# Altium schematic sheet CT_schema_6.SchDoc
size 478 x 453 mm
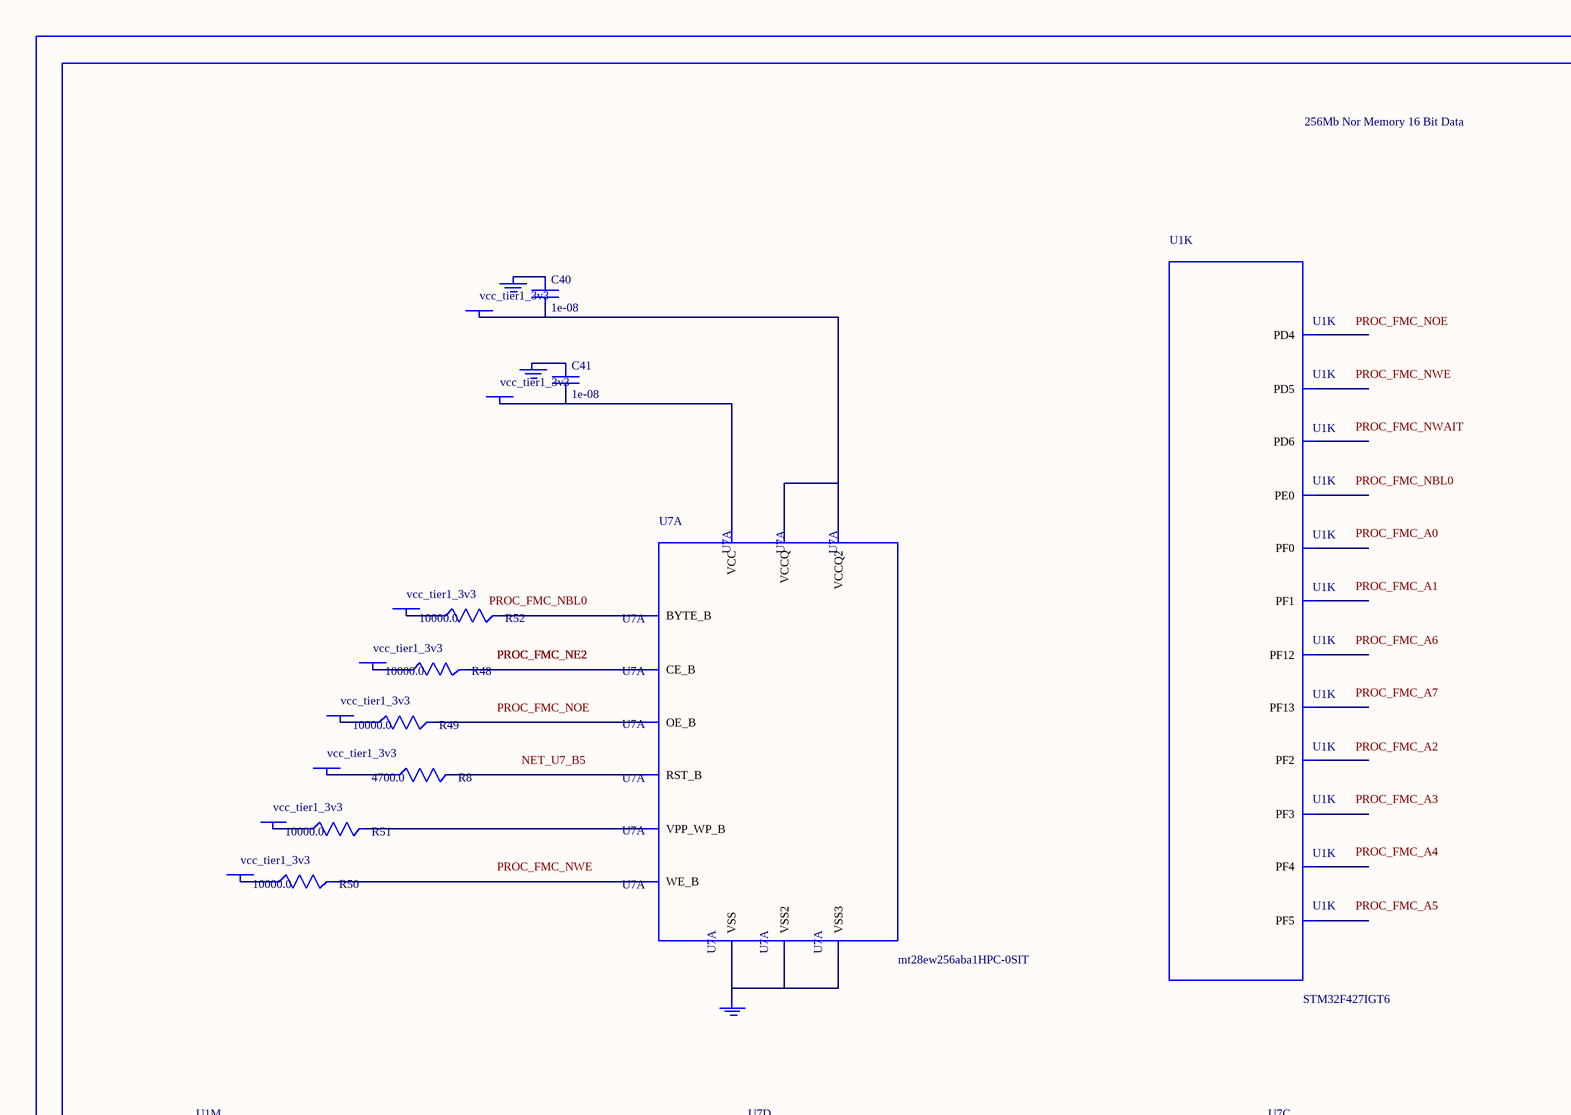
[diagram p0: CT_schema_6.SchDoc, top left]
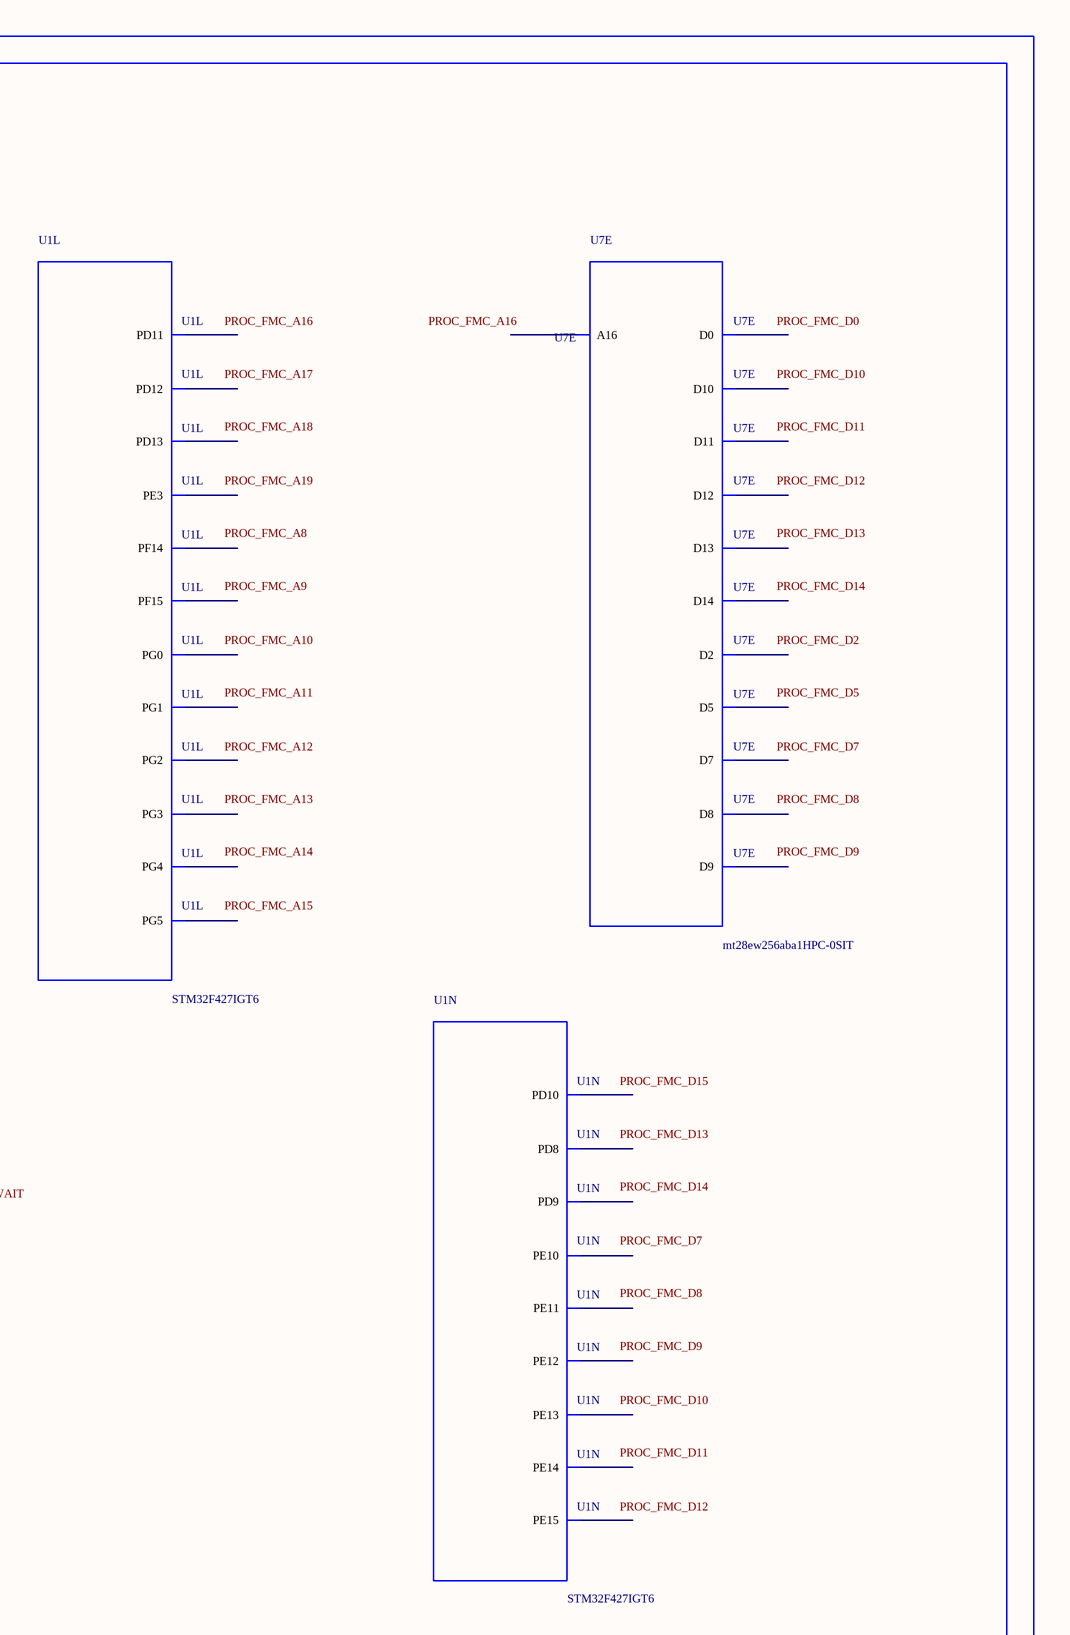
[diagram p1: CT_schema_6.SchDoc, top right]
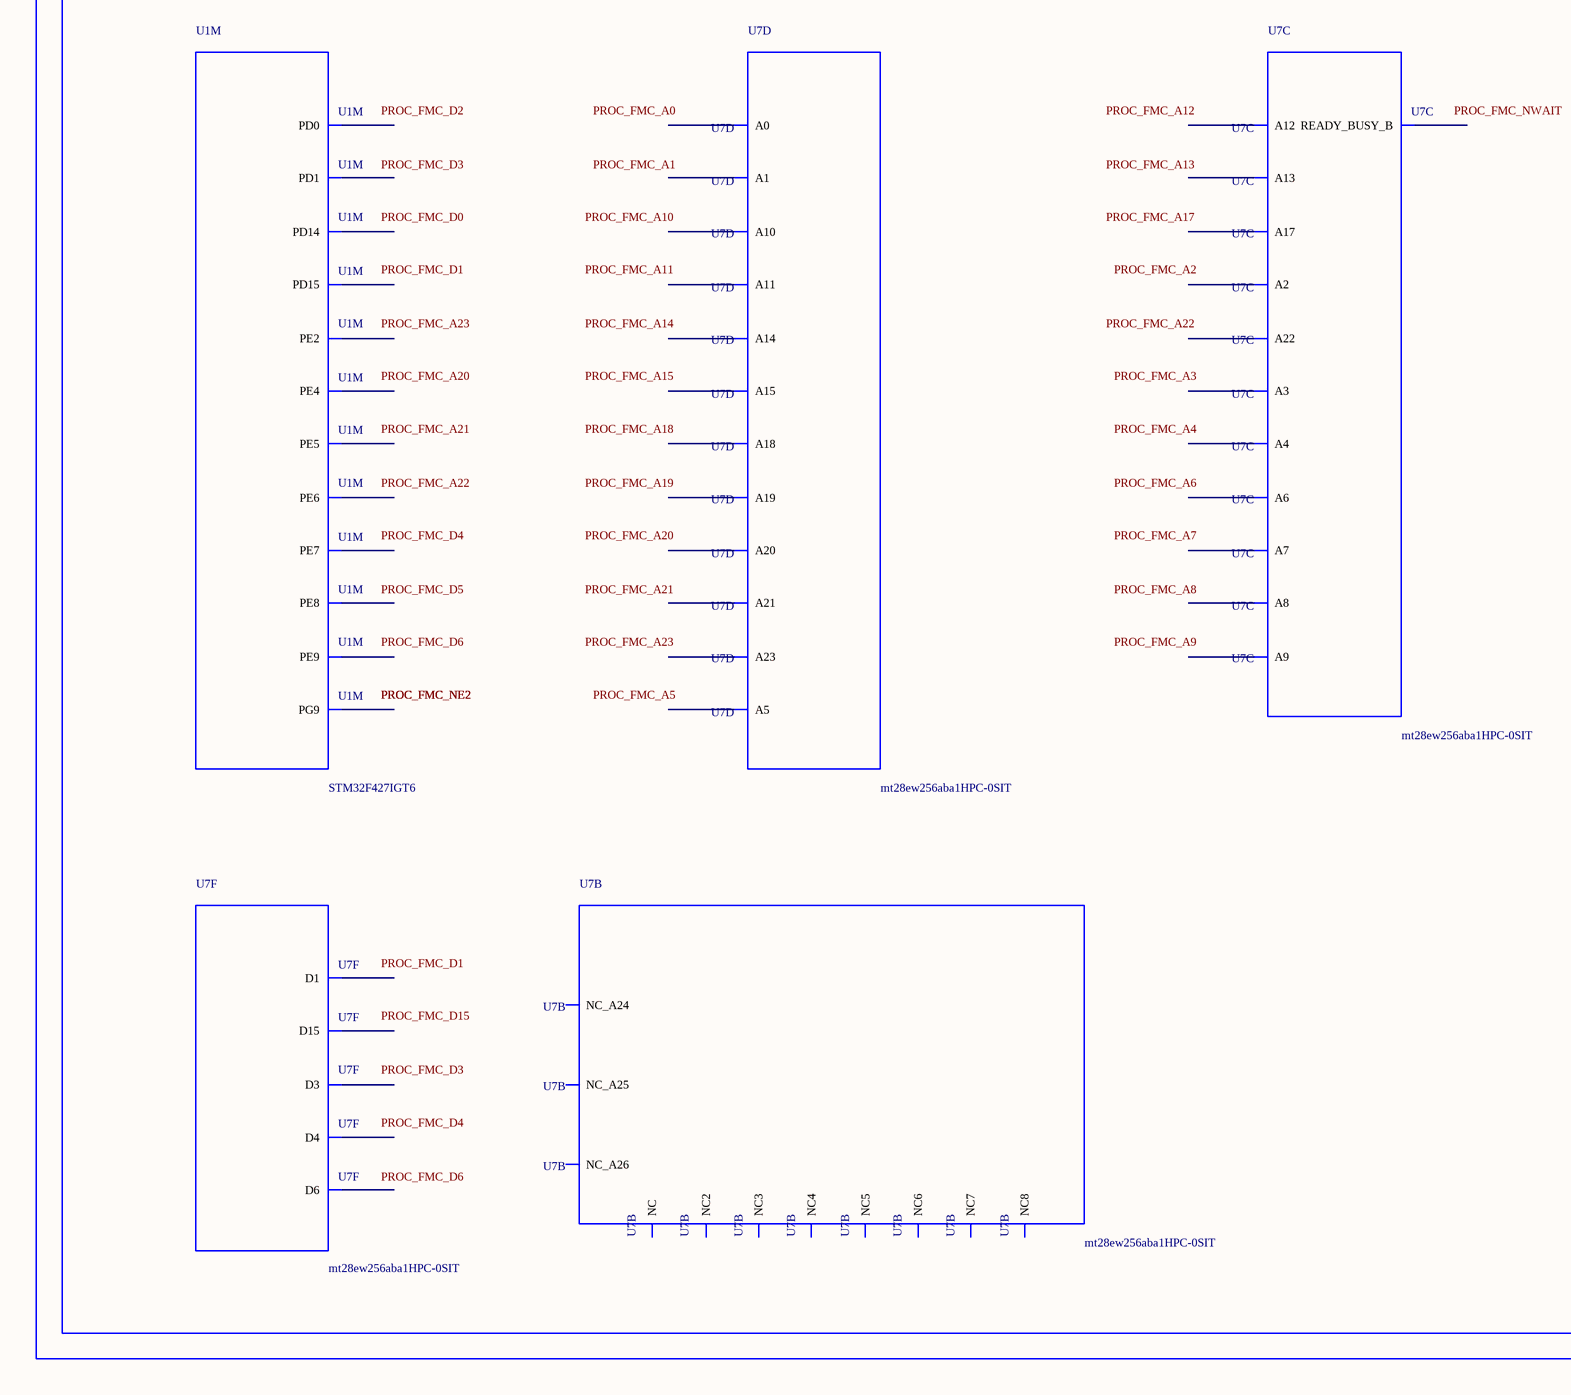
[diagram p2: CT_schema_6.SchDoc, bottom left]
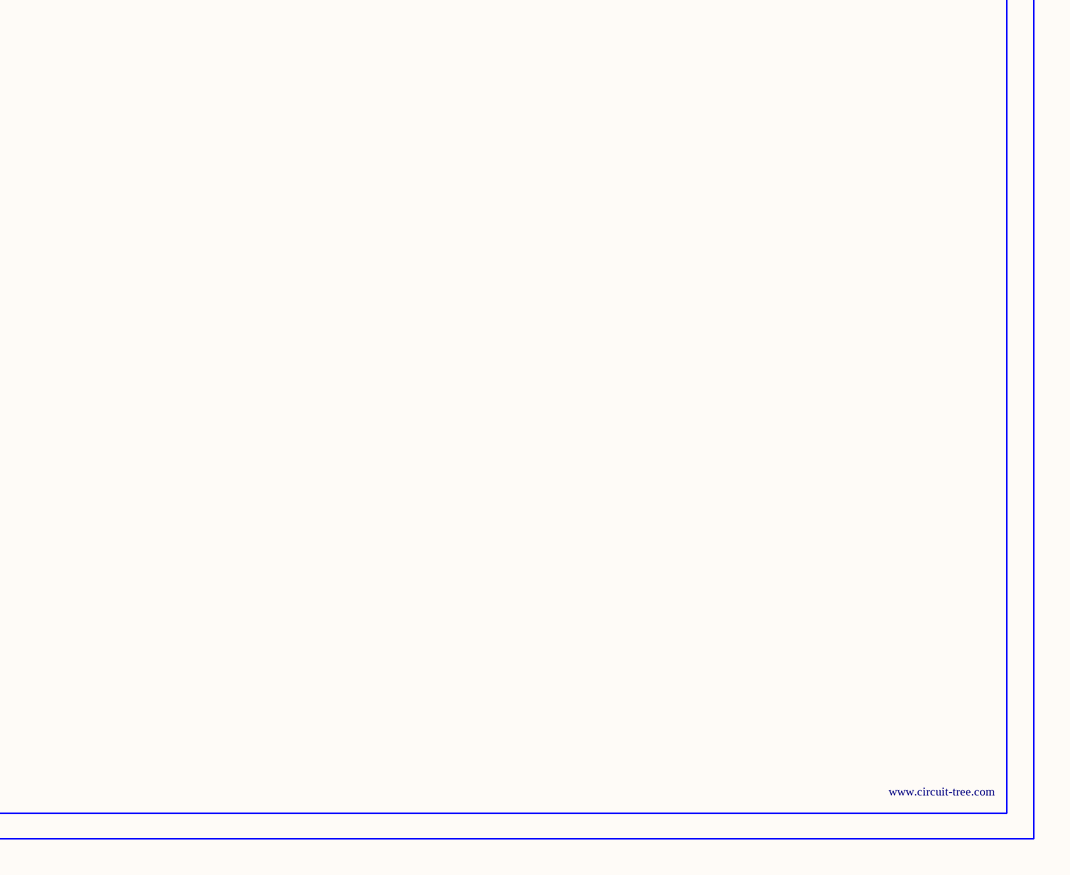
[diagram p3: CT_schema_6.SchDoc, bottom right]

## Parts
BORDER5  (no value)
C40  1e-08  [C0402]
C41  1e-08  [C0402]
GND_INSTANCE_5_0  (no value)
GND_INSTANCE_5_1  (no value)
GND_INSTANCE_5_2  (no value)
POWER_INSTANCE_5_0  vcc_tier1_3v3
POWER_INSTANCE_5_1  vcc_tier1_3v3
POWER_INSTANCE_5_2  vcc_tier1_3v3
POWER_INSTANCE_5_3  vcc_tier1_3v3
POWER_INSTANCE_5_4  vcc_tier1_3v3
POWER_INSTANCE_5_5  vcc_tier1_3v3
POWER_INSTANCE_5_6  vcc_tier1_3v3
POWER_INSTANCE_5_7  vcc_tier1_3v3
R8  4700.0  [R0603]
R48  10000.0  [R0603]
R49  10000.0  [R0603]
R50  10000.0  [R0603]
R51  10000.0  [R0603]
R52  10000.0  [R0603]
U1  STM32F427IGT6  [LQFP176]  (parts K,L,M,N of 14)
U7  mt28ew256aba1HPC-0SIT  [LBGA-64]  (parts A,B,C,D,E,F of 6)

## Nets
NetC40_1: C40.1 GND_INSTANCE_5_0.0(GND)
NetC40_2: C40.2 POWER_INSTANCE_5_0.0(PWR) U7.D8(VCCQ) U7.F1(VCCQ2)
NetC41_1: C41.1 GND_INSTANCE_5_1.0(GND)
NetC41_2: C41.2 POWER_INSTANCE_5_1.0(PWR) U7.G5(VCC)
NetGND_INSTANCE_5_2_0: GND_INSTANCE_5_2.0(GND) U7.E8(VSS) U7.H2(VSS2) U7.H7(VSS3)
NetPOWER_INSTANCE_5_2_0: POWER_INSTANCE_5_2.0(PWR) R48.1
NetPOWER_INSTANCE_5_3_0: POWER_INSTANCE_5_3.0(PWR) R49.1
NetPOWER_INSTANCE_5_4_0: POWER_INSTANCE_5_4.0(PWR) R50.1
NetPOWER_INSTANCE_5_5_0: POWER_INSTANCE_5_5.0(PWR) R51.1
NetPOWER_INSTANCE_5_6_0: POWER_INSTANCE_5_6.0(PWR) R52.1
NetPOWER_INSTANCE_5_7_0: POWER_INSTANCE_5_7.0(PWR) R8.1
NetR8_2: R8.2 U7.B5(RST_B)
NetR48_2: R48.2 U7.F2(CE_B)
NetR49_2: R49.2 U7.G2(OE_B)
NetR50_2: R50.2 U7.A5(WE_B)
NetR51_2: R51.2 U7.B4(VPP_WP_B)
NetR52_2: R52.2 U7.F7(BYTE_B)

Not connected (* = marked no-connect by the designer): U1 1(PE2) 2(PE3) 3(PE4) 4(PE5) 5(PE6) 16(PF0) 17(PF1) 18(PF2) 19(PF3) 20(PF4) 21(PF5) 60(PF12) 63(PF13) 64(PF14) 65(PF15) 66(PG0) 67(PG1) 68(PE7) 69(PE8) 70(PE9) 73(PE10) 74(PE11) 75(PE12) 76(PE13) 77(PE14) 78(PE15) 96(PD8) 97(PD9) 98(PD10) 99(PD11) 100(PD12) 101(PD13) 104(PD14) 105(PD15) 106(PG2) 107(PG3) 108(PG4) 109(PG5) 142(PD0) 143(PD1) 146(PD4) 147(PD5) 150(PD6) 152(PG9) 169(PE0); U7 A1(NC) A2(A3) A3(A7) A4(READY_BUSY_B) A6(A9) A7(A13) A8(NC2) B1(NC_A26) B2(A4) B3(A17) B6(A8) B7(A12) B8(A22) C1(NC3) C2(A2) C3(A6) C4(A18) C5(A21) C6(A10) C7(A14) C8(A23) D1(NC4) D2(A1) D3(A5) D4(A20) D5(A19) D6(A11) D7(A15) E1(NC5) E2(A0) E3(D0) E4(D2) E5(D5) E6(D7) E7(A16) F3(D8) F4(D10) F5(D12) F6(D14) F8(NC_A24) G1(NC6) G3(D9) G4(D11) G6(D13) G7(D15) G8(NC_A25) H1(NC7) H3(D1) H4(D3) H5(D4) H6(D6) H8(NC8)

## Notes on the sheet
- Labels drawn without touching a wire or pin: NET_U7_B5, PROC_FMC_A0, PROC_FMC_A1, PROC_FMC_A2, PROC_FMC_A3, PROC_FMC_A4, PROC_FMC_A5, PROC_FMC_A6, PROC_FMC_A7, PROC_FMC_A8, PROC_FMC_A9, PROC_FMC_A10, PROC_FMC_A11, PROC_FMC_A12, PROC_FMC_A13, PROC_FMC_A14, PROC_FMC_A15, PROC_FMC_A16, PROC_FMC_A17, PROC_FMC_A18, PROC_FMC_A19, PROC_FMC_A20, PROC_FMC_A21, PROC_FMC_A22, PROC_FMC_A23, PROC_FMC_D0, PROC_FMC_D1, PROC_FMC_D2, PROC_FMC_D3, PROC_FMC_D4, PROC_FMC_D5, PROC_FMC_D6, PROC_FMC_D7, PROC_FMC_D8, PROC_FMC_D9, PROC_FMC_D10, PROC_FMC_D11, PROC_FMC_D12, PROC_FMC_D13, PROC_FMC_D14, PROC_FMC_D15, PROC_FMC_NBL0, PROC_FMC_NOE, PROC_FMC_NWAIT, PROC_FMC_NWE

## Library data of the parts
BORDER5 = BORDER_PAGE5
C40 C41 = C0402C103K3RAC
GND_INSTANCE_5_0-GND_INSTANCE_5_2 = GND
POWER_INSTANCE_5_0-POWER_INSTANCE_5_7 = PWR
R8 = RC0603JR-074K7L
R48-R52 = RC0603JR-0710KL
